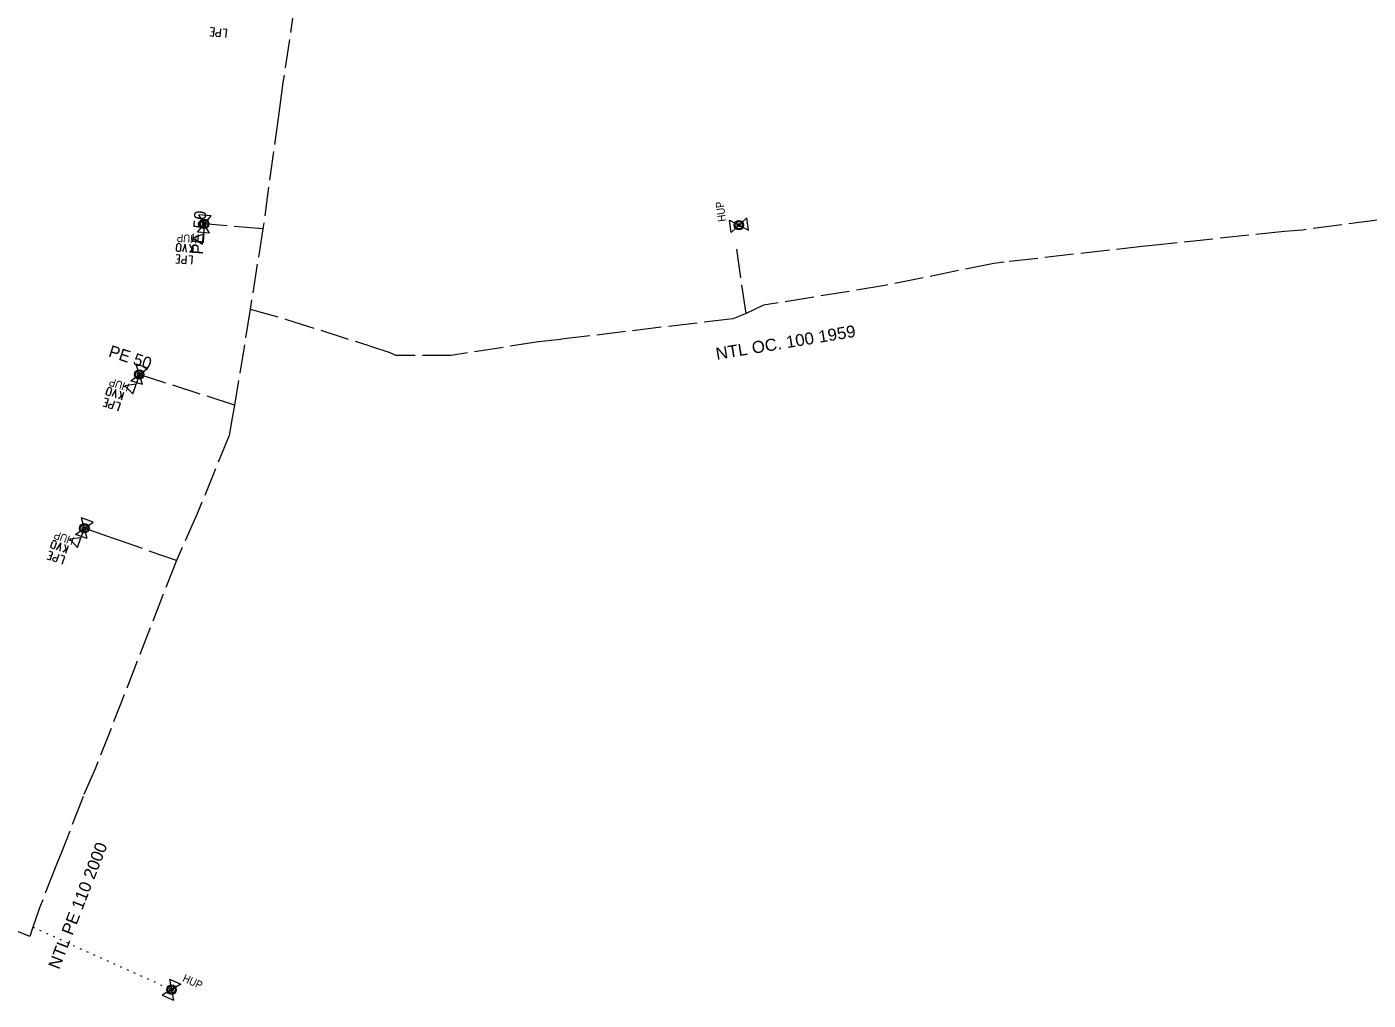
# Model space of a CAD drawing. Extents: x -688140 to -687678, y -1056859 to -1056384.
# Drawn here: x -687935 to -687851.2, y -1056613.6 to -1056552.8 of the extents above; entities that cross this region are included whole.
import ezdxf
from ezdxf.enums import TextEntityAlignment as Align

# ---------------------------------------------------------------- set-up
doc = ezdxf.new("R2010")
doc.units = 0
doc.header["$LTSCALE"] = 0.3
doc.linetypes.add('DOTTED', pattern=[1.5, 0.3, -1.2])
doc.linetypes.add('LONG_DASHED', pattern=[7.5, 6, -1.5])
for name, color, linetype, lineweight in [('12', 7, 'Continuous', 13), ('35', 7, 'LONG_DASHED', 13), ('50', 7, 'LONG_DASHED', 13), ('51', 7, 'DOTTED', 13)]:
    doc.layers.add(name, color=color, linetype=linetype, lineweight=lineweight)
doc.layers.add('15', color=7, linetype='Continuous')

msp = doc.modelspace()

# ---------------------------------------------------------------- linework, layer by layer
at = {"layer": '12'}
for p, q in [((-687923.431, -1056553.125), (-687923.272, -1056553.143)), ((-687923.044, -1056553.179), (-687922.885, -1056553.197)), ((-687924.308, -1056565.652), (-687923.452, -1056564.628)), ((-687923.452, -1056564.628), (-687924.219, -1056564.565)), ((-687923.541, -1056565.715), (-687924.219, -1056564.565)), ((-687890.965, -1056565.674), (-687889.993, -1056564.76)), ((-687889.886, -1056565.522), (-687889.993, -1056564.76)), ((-687923.541, -1056565.715), (-687924.308, -1056565.652)), ((-687923.88, -1056565.14), (-687923.931, -1056565.768)), ((-687891.072, -1056564.912), (-687889.886, -1056565.522)), ((-687890.965, -1056565.674), (-687891.072, -1056564.912)), ((-687925.618, -1056566.764), (-687925.593, -1056566.455)), ((-687925.344, -1056566.475), (-687925.369, -1056566.784)), ((-687924.642, -1056566.733), (-687924.787, -1056566.42)), ((-687924.599, -1056566.937), (-687924.558, -1056566.439)), ((-687925.573, -1056567.319), (-687925.414, -1056567.332)), ((-687924.574, -1056566.628), (-687924.798, -1056566.921)), ((-687925.185, -1056567.361), (-687925.026, -1056567.374)), ((-687927.406, -1056574.14), (-687928.139, -1056573.903)), ((-687927.741, -1056575.177), (-687928.139, -1056573.903)), ((-687928.474, -1056574.94), (-687927.406, -1056574.14)), ((-687927.94, -1056574.54), (-687928.133, -1056575.14)), ((-687930.003, -1056575.724), (-687929.908, -1056575.429)), ((-687929.67, -1056575.505), (-687929.765, -1056575.8)), ((-687929.046, -1056575.917), (-687929.116, -1056575.579)), ((-687929.051, -1056576.126), (-687928.897, -1056575.65)), ((-687927.741, -1056575.177), (-687928.474, -1056574.94)), ((-687930.086, -1056576.275), (-687929.934, -1056576.324)), ((-687929.718, -1056576.404), (-687929.566, -1056576.453)), ((-687928.955, -1056575.831), (-687929.241, -1056576.064)), ((-687931.914, -1056584.537), (-687930.826, -1056583.763)), ((-687930.826, -1056583.763), (-687931.553, -1056583.508)), ((-687931.187, -1056584.792), (-687931.553, -1056583.508)), ((-687931.187, -1056584.792), (-687931.914, -1056584.537)), ((-687931.37, -1056584.15), (-687931.579, -1056584.744)), ((-687933.463, -1056585.28), (-687933.36, -1056584.988)), ((-687933.124, -1056585.071), (-687933.227, -1056585.363)), ((-687932.418, -1056585.414), (-687932.71, -1056585.64)), ((-687932.511, -1056585.498), (-687932.572, -1056585.159)), ((-687932.521, -1056585.707), (-687932.355, -1056585.235)), ((-687933.56, -1056585.829), (-687933.409, -1056585.882)), ((-687933.196, -1056585.968), (-687933.045, -1056586.021)), ((-687926.049, -1056612.32), (-687925.795, -1056613.63)), ((-687926.049, -1056612.32), (-687925.347, -1056612.636)), ((-687925.347, -1056612.636), (-687926.497, -1056613.314)), ((-687926.497, -1056613.314), (-687925.795, -1056613.63))]:
    msp.add_line(p, q, dxfattribs=at)
for points in [[(-687923.52, -1056553.377), (-687923.301, -1056553.402), (-687923.245, -1056552.905), (-687923.483, -1056552.878)], [(-687922.857, -1056552.949), (-687922.913, -1056553.445), (-687923.072, -1056553.427)], [(-687922.526, -1056553.489), (-687922.47, -1056552.993), (-687922.698, -1056552.967)], [(-687923.072, -1056553.427), (-687923.12, -1056553.402), (-687923.151, -1056553.318), (-687923.146, -1056553.278), (-687923.096, -1056553.193), (-687923.044, -1056553.179)], [(-687925.344, -1056566.475), (-687925.34, -1056566.435), (-687925.359, -1056566.414), (-687925.396, -1056566.381), (-687925.435, -1056566.367), (-687925.485, -1056566.363), (-687925.515, -1056566.361), (-687925.558, -1056566.397), (-687925.58, -1056566.416), (-687925.593, -1056566.455)], [(-687924.978, -1056566.906), (-687925.076, -1056566.397), (-687925.237, -1056566.885)], [(-687925.654, -1056567.573), (-687925.435, -1056567.591), (-687925.394, -1056567.093), (-687925.633, -1056567.074)], [(-687925.369, -1056566.784), (-687925.371, -1056566.814), (-687925.394, -1056566.842), (-687925.436, -1056566.869), (-687925.476, -1056566.866), (-687925.526, -1056566.862), (-687925.556, -1056566.859), (-687925.592, -1056566.816), (-687925.611, -1056566.794), (-687925.618, -1056566.764)], [(-687925.006, -1056567.125), (-687925.046, -1056567.623), (-687925.206, -1056567.61)], [(-687924.658, -1056567.655), (-687924.617, -1056567.157), (-687924.846, -1056567.138)], [(-687925.206, -1056567.61), (-687925.254, -1056567.586), (-687925.287, -1056567.503), (-687925.284, -1056567.463), (-687925.237, -1056567.377), (-687925.185, -1056567.361)], [(-687929.765, -1056575.8), (-687929.774, -1056575.829), (-687929.803, -1056575.851), (-687929.85, -1056575.868), (-687929.888, -1056575.855), (-687929.936, -1056575.84), (-687929.964, -1056575.831), (-687929.99, -1056575.78), (-687930.003, -1056575.755), (-687930.003, -1056575.724)], [(-687929.67, -1056575.505), (-687929.658, -1056575.467), (-687929.671, -1056575.442), (-687929.699, -1056575.401), (-687929.734, -1056575.38), (-687929.782, -1056575.364), (-687929.811, -1056575.355), (-687929.861, -1056575.381), (-687929.886, -1056575.394), (-687929.908, -1056575.429)], [(-687929.412, -1056576.009), (-687929.392, -1056575.49), (-687929.66, -1056575.929)], [(-687930.223, -1056576.504), (-687930.014, -1056576.571), (-687929.86, -1056576.095), (-687930.089, -1056576.022)], [(-687929.795, -1056576.642), (-687929.836, -1056576.608), (-687929.85, -1056576.519), (-687929.838, -1056576.481), (-687929.772, -1056576.408), (-687929.718, -1056576.404)], [(-687929.489, -1056576.215), (-687929.643, -1056576.691), (-687929.795, -1056576.642)], [(-687929.272, -1056576.811), (-687929.118, -1056576.335), (-687929.337, -1056576.264)], [(-687933.124, -1056585.071), (-687933.111, -1056585.033), (-687933.123, -1056585.007), (-687933.151, -1056584.966), (-687933.185, -1056584.943), (-687933.233, -1056584.927), (-687933.261, -1056584.917), (-687933.312, -1056584.941), (-687933.337, -1056584.953), (-687933.36, -1056584.988)], [(-687933.703, -1056586.054), (-687933.495, -1056586.127), (-687933.33, -1056585.656), (-687933.556, -1056585.576)], [(-687933.227, -1056585.363), (-687933.237, -1056585.391), (-687933.266, -1056585.413), (-687933.313, -1056585.428), (-687933.351, -1056585.415), (-687933.398, -1056585.398), (-687933.427, -1056585.388), (-687933.451, -1056585.337), (-687933.463, -1056585.312), (-687933.463, -1056585.28)], [(-687932.879, -1056585.581), (-687932.846, -1056585.062), (-687933.125, -1056585.494)], [(-687933.278, -1056586.204), (-687933.319, -1056586.168), (-687933.33, -1056586.079), (-687933.317, -1056586.042), (-687933.249, -1056585.97), (-687933.196, -1056585.968)], [(-687932.962, -1056585.785), (-687933.127, -1056586.257), (-687933.278, -1056586.204)], [(-687932.76, -1056586.386), (-687932.594, -1056585.914), (-687932.811, -1056585.838)]]:
    msp.add_lwpolyline(points, dxfattribs=at)
for points in [[(-687923.931, -1056565.768), (-687924.585, -1056566.035), (-687923.984, -1056566.406)], [(-687928.133, -1056575.14), (-687928.831, -1056575.251), (-687928.33, -1056575.749)], [(-687931.579, -1056584.744), (-687932.279, -1056584.838), (-687931.791, -1056585.348)]]:
    msp.add_lwpolyline(points, close=True, dxfattribs=at)
for centre, radius in [((-687923.88, -1056565.14), 0.297), ((-687923.88, -1056565.14), 0.223), ((-687923.88, -1056565.14), 0.223), ((-687923.88, -1056565.14), 0.112), ((-687890.479, -1056565.217), 0.297), ((-687890.479, -1056565.217), 0.223), ((-687890.479, -1056565.217), 0.223), ((-687890.479, -1056565.217), 0.112), ((-687927.94, -1056574.54), 0.297), ((-687927.94, -1056574.54), 0.223), ((-687927.94, -1056574.54), 0.223), ((-687927.94, -1056574.54), 0.112), ((-687931.37, -1056584.15), 0.297), ((-687931.37, -1056584.15), 0.223), ((-687931.37, -1056584.15), 0.223), ((-687931.37, -1056584.15), 0.112), ((-687925.922, -1056612.975), 0.297), ((-687925.922, -1056612.975), 0.223), ((-687925.922, -1056612.975), 0.223), ((-687925.922, -1056612.975), 0.112)]:
    msp.add_circle(centre, radius, dxfattribs=at)
at = {"layer": '35'}
for points in [[(-687918.23, -1056551.39), (-687918.96, -1056556.31), (-687919.045, -1056556.948), (-687919.242, -1056558.391), (-687920.21, -1056565.44), (-687921.01, -1056570.47)], [(-687848.35, -1056564.61), (-687855.26, -1056565.52), (-687856.39, -1056565.61), (-687864.24, -1056566.44), (-687865.1, -1056566.53)], [(-687865.1, -1056566.53), (-687873.91, -1056567.53), (-687874.56, -1056567.61), (-687881.36, -1056568.99), (-687888.94, -1056570.22), (-687890.03, -1056570.73), (-687890.86, -1056571.06), (-687901.6, -1056572.35), (-687902.99, -1056572.5), (-687908.45, -1056573.36), (-687911.9, -1056573.35), (-687912.34, -1056573.16)], [(-687921.01, -1056570.47), (-687921.99, -1056576.46), (-687922.13, -1056577.25), (-687922.32, -1056578.35), (-687924.34, -1056583.3), (-687925.62, -1056586.17), (-687930.67, -1056599.14), (-687931.44, -1056600.9), (-687931.469, -1056600.974), (-687932.74, -1056604.24), (-687933.15, -1056605.26), (-687934.17, -1056607.86), (-687934.46, -1056608.712), (-687934.582, -1056609.07), (-687934.78, -1056609.65), (-687944.75, -1056605.61), (-687953.7, -1056602.04), (-687955.74, -1056598.63), (-687956.136, -1056597.968), (-687956.28, -1056597.73)], [(-687921.01, -1056570.47), (-687918.74, -1056571.1), (-687913.599, -1056572.741), (-687913.501, -1056572.773), (-687912.34, -1056573.16)]]:
    msp.add_lwpolyline(points, dxfattribs=at)
at = {"layer": '50'}
for p, q in [((-687920.21, -1056565.44), (-687923.88, -1056565.14)), ((-687890.03, -1056570.73), (-687890.65, -1056566.48)), ((-687921.99, -1056576.46), (-687927.94, -1056574.54))]:
    msp.add_line(p, q, dxfattribs=at)
msp.add_lwpolyline([(-687925.62, -1056586.17), (-687929.044, -1056584.966), (-687929.547, -1056584.789), (-687931.37, -1056584.15)], dxfattribs=at)
at = {"layer": '51'}
msp.add_line((-687934.582, -1056609.07), (-687925.922, -1056612.975), dxfattribs=at)

# ---------------------------------------------------------------- texts
at = {"layer": '12', "width": 0.9}
for rotation, p in [(97.999, (-687891.361, -1056564.331)), (175.325, (-687924.938, -1056565.806)), (162.118, (-687929.122, -1056574.947)), (160.646, (-687932.562, -1056584.526)), (335.73, (-687924.702, -1056612.702))]:
    msp.add_text('HUP', height=0.5, rotation=rotation, dxfattribs=at).set_placement(p, align=Align.CENTER)
at = {"layer": '15'}
for rotation, p in [(85.327, (-687923.962, -1056567.071)), (342.116, (-687929.912, -1056573.409))]:
    msp.add_text('PE 50', height=0.75, rotation=rotation, dxfattribs=at).set_placement(p)
at = {"layer": '15', "width": 1.05}
for s, rotation, p in [('NTL OC. 100 1959', 9.418, (-687891.858, -1056573.63)), ('NTL PE 110 2000', 68.726, (-687932.95, -1056611.755))]:
    msp.add_text(s, height=0.75, rotation=rotation, dxfattribs=at).set_placement(p)

doc.saveas('drawing.dxf')
